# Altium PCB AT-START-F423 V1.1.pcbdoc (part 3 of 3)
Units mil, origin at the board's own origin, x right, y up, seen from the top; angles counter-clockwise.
Board outline 13392.89 x 3532.45 mil, 2 copper layers (Top Layer, Bottom Layer); 137 components, 162 nets, 618 pads, 618 vias.
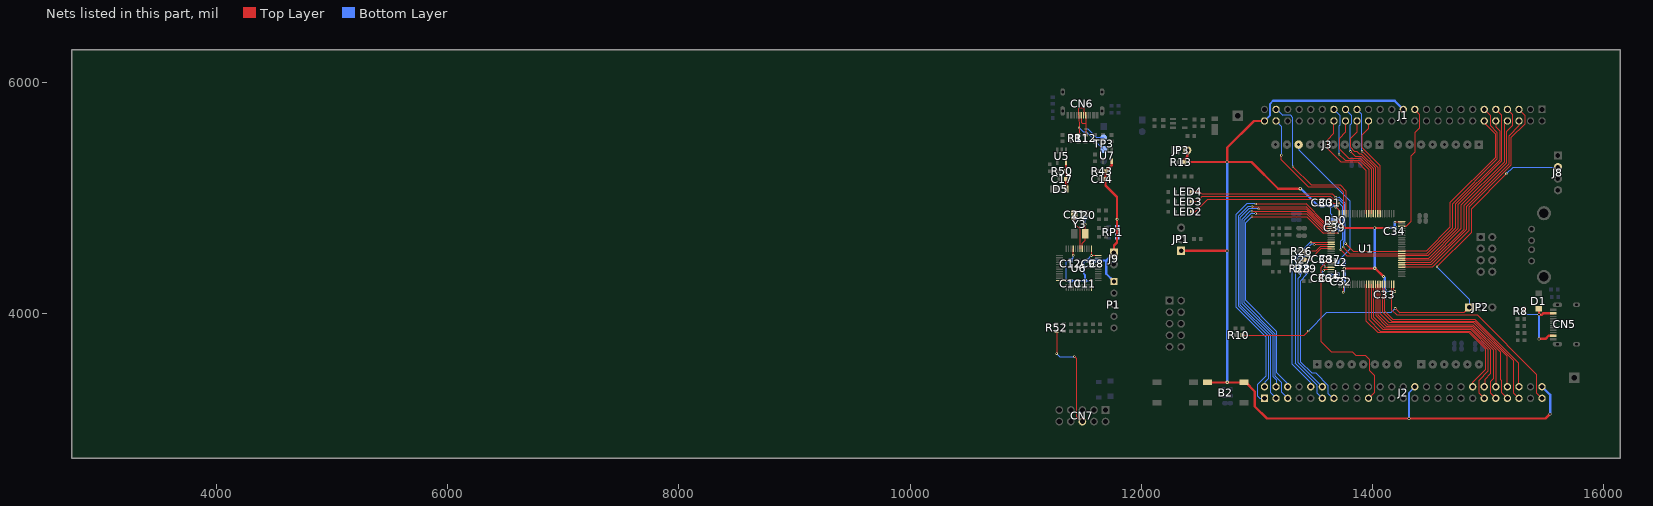
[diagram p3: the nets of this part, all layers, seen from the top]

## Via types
v1: diameter 19.68, hole 7.87, Top Layer to Bottom Layer, 317 vias
v2: diameter 19.7, hole 7.9, Top Layer to Bottom Layer, 187 vias
v3: diameter 19.7, hole 7.87, Top Layer to Bottom Layer, 72 vias
v4: diameter 27.56, hole 15.75, Top Layer to Bottom Layer, 31 vias
v5: diameter 23.62, hole 11.81, Top Layer to Bottom Layer, 11 vias

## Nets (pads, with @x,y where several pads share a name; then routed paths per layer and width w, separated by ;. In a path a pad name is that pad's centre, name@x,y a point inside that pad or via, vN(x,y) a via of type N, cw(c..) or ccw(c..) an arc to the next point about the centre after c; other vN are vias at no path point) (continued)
PD1: J1.32 U1.82 | length 889.2
  Top Layer w6: J1.32@13965.15,5665.15 13965.15,5600.69 13909.58,5545.11 13909.58,5432.11 14064.67,5277.01 U1.82@14064.67,4863.21
PD2: J1.33 U1.83 | length 976.4
  Top Layer w6: v3(13908.58,5402.11) 14044.98,5265.71 U1.83@14044.98,4863.21
  Bottom Layer w6: J1.33@13865.15,5765.15 13907.58,5722.73 13907.58,5403.11 v3(13908.58,5402.11)
PD3: J1.34 U1.84 | length 936.4
  Top Layer w6: J1.34@13865.15,5665.15 13865.15,5571.17 13810.58,5516.59 13810.58,5435.92 13846.38,5400.11 13868.58,5400.11 13890.58,5378.11 13907.58,5378.11 14025.27,5260.41 U1.84@14025.27,4863.21
PD4: J1.35 U1.85 | length 1036.1
  Top Layer w6: v3(13808.58,5402.11) 13850.58,5360.11 13899.58,5360.11 14005.67,5254.01 U1.85@14005.67,4863.21
  Bottom Layer w6: J1.35@13765.15,5765.15 13815.58,5714.73 13815.58,5639.11 13808.58,5632.11 v3(13808.58,5402.11)
PD5: J1.36 U1.86 | length 999.8
  Top Layer w6: J1.36@13765.15,5665.15 13765.15,5568.23 13709.58,5512.66 13709.58,5425.11 13791.58,5343.11 13894.58,5343.11 13985.98,5251.71 U1.86@13985.98,4863.21
PD6: J1.37 U1.87 | length 1106.9
  Top Layer w6: v3(13708.58,5377.11) 13761.58,5324.11 13888.58,5324.11 13966.27,5246.41 U1.87@13966.27,4863.21
  Bottom Layer w6: J1.37@13665.15,5765.15 13715.58,5714.73 13715.58,5628.11 13709.58,5622.11 13709.58,5378.11 v3(13708.58,5377.11)
PD7: J1.38 U1.88 | length 1049.8
  Top Layer w6: J1.38@13665.15,5665.15 13665.15,5557.69 13610.58,5503.11 13610.58,5424.11 13727.58,5307.11 13874.58,5307.11 13946.58,5235.11 U1.88@13946.58,4863.21
PD8: J1.5 U1.55 | length 1980.1
  Top Layer w6: U1.55@14251.67,4400.61 14515.91,4400.61 14830.58,4715.28 14830.58,4917.28 15195.58,5282.28 15195.58,5518.11 15314.58,5637.11 15314.58,5715.73 J1.5@15265.15,5765.15
PD9: J1.6 U1.56 | length 1814.6
  Top Layer w6: U1.56@14251.67,4420.31 14507.61,4420.31 14809.58,4722.28 14809.58,4924.28 15176.58,5291.28 15176.58,5534.11 15265.15,5622.69 J1.6@15265.15,5665.15
PD10: J1.7 U1.57 | length 1884.3
  Top Layer w6: U1.57@14251.67,4440.01 14500.31,4440.01 14786.58,4726.28 14786.58,4931.28 15156.58,5301.28 15156.58,5573.09 15207.58,5624.09 15207.58,5722.73 J1.7@15165.15,5765.15
PD11: J1.8 U1.58 | length 1724.6
  Top Layer w6: U1.58@14251.67,4459.71 14492.01,4459.71 14763.58,4731.28 14763.58,4936.28 15136.58,5309.28 15136.58,5636.58 J1.8@15165.15,5665.15
PD12: J1.9 U1.59 | length 1802.6
  Top Layer w6: U1.59@14251.67,4479.41 14484.71,4479.41 14741.58,4736.28 14741.58,4944.28 15117.58,5320.28 15117.58,5712.73 J1.9@15065.15,5765.15
PD13/LED2: J1.10 LED2.2 U1.60 | length 3958.6
  Top Layer w6: LED2.2@12436.83,4879.28 12466.58,4879.28 12574.89,4987.6 13625.89,4987.6 13659.38,4954.11 v3(13709.58,4954.11) ; v3(13725.58,4551.11) 13777.67,4499.01 U1.60@14251.67,4499.01 14476.31,4499.01 14716.58,4739.28 14716.58,4946.28 15097.58,5327.28 15097.58,5581.11 15065.15,5613.54 J1.10@15065.15,5665.15
  Bottom Layer w6: v3(13709.58,4954.11) 13735.58,4928.11 13735.58,4638.11 13725.58,4628.11 v3(13725.58,4551.11)
PD14/LED3: J1.11 LED3.2 U1.61 | length 4025.4
  Top Layer w6: LED3.2@12435.83,4965.28 12476.58,4965.28 12520.89,5009.6 13639.89,5009.6 13667.38,4982.11 v3(13700.58,4982.11) ; v3(13746.58,4575.11) 13802.98,4518.71 U1.61@14251.67,4518.71 14470.01,4518.71 14691.58,4740.28 14691.58,4949.28 15079.58,5337.28 15079.58,5564.11 15021.58,5622.11 15021.58,5708.73 J1.11@14965.15,5765.15
  Bottom Layer w6: v3(13700.58,4982.11) 13713.58,4982.11 13749.58,4946.11 13749.58,4626.47 13744.58,4621.47 13744.58,4577.11 v3(13746.58,4575.11)
PD15/LED4: J1.12 LED4.2 U1.62 | length 3854.8
  Top Layer w6: LED4.2@12434.83,5051.28 12503.96,5051.28 12524.98,5030.26 13656.42,5030.26 v3(13681.58,5005.11) ; v3(13766.58,4604.11) 13832.27,4538.41 U1.62@14251.67,4538.41 14461.71,4538.41 14668.5,4745.21 14668.5,4956.21 15059.58,5347.28 15059.58,5553.11 14965.15,5647.54 J1.12@14965.15,5665.15
  Bottom Layer w6: v3(13681.58,5005.11) 13710.37,5005.11 13763.58,4951.91 13763.58,4607.11 v3(13766.58,4604.11)
PE0: J1.47 U1.97 | length 1342.8
  Top Layer w6: v3(13310.58,5271.11) 13467.58,5114.11 13718.58,5114.11 13769.38,5063.31 U1.97@13769.38,4863.21
  Bottom Layer w6: J1.47@13165.15,5765.15 13170.54,5765.15 13221.58,5714.11 13290.58,5714.11 13310.58,5694.11 v3(13310.58,5271.11)
PE1: J1.48 U1.98 | length 1195.8
  Top Layer w6: v3(13210.58,5368.11) 13210.58,5328.11 13447.58,5091.11 13706.58,5091.11 13749.77,5047.91 U1.98@13749.77,4863.21
  Bottom Layer w6: J1.48@13165.15,5665.15 13210.58,5619.73 v3(13210.58,5368.11)
PE2: J2.1 U1.1 | length 2698.9
  Top Layer w6: v3(12988.58,4947.11) 13425.58,4947.11 13578.38,4794.31 U1.1@13641.48,4794.31
  Bottom Layer w6: v3(12988.58,4947.11) 12912.58,4947.11 12904.58,4939.11 12904.42,4939.11 12818.58,4853.27 12818.58,4056.91 13077.58,3797.91 13077.58,3457.11 13002.58,3382.11 13002.58,3290.11 13026.12,3266.57 J2.1@13065.15,3266.57
PE3: J2.2 U1.2 | length 2495.9
  Top Layer w6: v3(12958.58,4925.11) 13427.78,4925.11 13578.28,4774.61 U1.2@13641.48,4774.61
  Bottom Layer w6: v3(12958.58,4925.11) 12921.58,4925.11 12916.58,4920.11 12916.25,4920.11 12836.58,4840.43 12836.58,4065.91 13095.36,3807.13 13095.36,3437.89 13065.15,3407.69 J2.2@13065.15,3366.57
PE4: J2.3 U1.3 | length 2573.4
  Top Layer w6: v3(13012.58,4905.11) 13427.98,4905.11 13578.08,4755.01 U1.3@13641.48,4755.01
  Bottom Layer w6: v3(13012.58,4905.11) 12930.58,4905.11 12852.58,4827.11 12852.58,4077.91 13114.58,3815.91 13114.58,3317.14 J2.3@13165.15,3266.57
PE5: J2.4 U1.4 | length 2433.6
  Top Layer w6: v3(12956.58,4884.11) 13429.18,4884.11 13577.98,4735.31 U1.4@13641.48,4735.31
  Bottom Layer w6: v3(12956.58,4884.11) 12955.58,4883.11 12939.58,4883.11 12867.58,4811.11 12867.58,4087.91 13134.29,3821.2 13134.29,3456.11 13165.15,3425.25 J2.4@13165.15,3366.57
PE6: J2.5 U1.5 | length 2538.7
  Top Layer w6: v3(12988.58,4864.11) 13429.38,4864.11 13577.88,4715.61 U1.5@13641.48,4715.61
  Bottom Layer w6: v3(12988.58,4864.11) 12945.58,4864.11 12883.58,4802.11 12883.58,4096.91 13154.11,3826.38 13154.11,3460.58 13208.6,3406.08 13208.6,3323.11 J2.5@13265.15,3266.57
PE7: J2.38 U1.38 | length 1822.5
  Top Layer w6: U1.38@13946.58,4253.01 13946.58,3934.11 14046.58,3834.11 14835.98,3834.11 14977.58,3692.51 14977.58,3520.11 14865.15,3407.69 J2.38@14865.15,3366.57
PE8: J2.39 U1.39 | length 1920
  Top Layer w6: U1.39@13966.27,4253.01 13966.27,3949.41 14067.58,3848.11 14841.78,3848.11 14997.58,3692.31 14997.58,3500.11 14917.58,3420.11 14917.58,3314.14 J2.39@14965.15,3266.57
PE9: J2.40 U1.40 | length 1782.1
  Top Layer w6: U1.40@13985.98,4253.01 13985.98,3962.71 14086.58,3862.11 14847.58,3862.11 15018.58,3691.11 15018.58,3479.11 14968.46,3429 14968.46,3369.88 J2.40@14965.15,3366.57
PE10: J2.41 U1.41 | length 1886.2
  Top Layer w6: U1.41@14005.67,4253.01 14005.67,3973.01 14102.58,3876.11 14853.98,3876.11 15041.58,3688.51 15041.58,3434.11 15016.58,3409.11 15016.58,3315.14 J2.41@15065.15,3266.57
PE11: J2.42 U1.42 | length 1751.4
  Top Layer w6: U1.42@14025.27,4253.01 14025.27,3983.41 14118.58,3890.11 14859.78,3890.11 15063.58,3686.31 15063.58,3430.11 15065.15,3428.54 J2.42@15065.15,3366.57
PE12: J2.43 U1.43 | length 1881
  Top Layer w6: U1.43@14044.98,4253.01 14044.98,3989.71 14130.58,3904.11 14865.58,3904.11 15101.58,3668.11 15101.58,3433.11 15113.58,3421.11 15113.58,3318.14 J2.43@15165.15,3266.57
PE13: J2.44 U1.44 | length 1771.1
  Top Layer w6: U1.44@14064.67,4253.01 14064.67,3997.01 14143.58,3918.11 14875.58,3918.11 15165.15,3628.54 J2.44@15165.15,3366.57
PE14: J2.45 U1.45 | length 1894.4
  Top Layer w6: U1.45@14084.38,4253.01 14084.38,4014.11 14166.37,3932.11 14881.38,3932.11 15217.58,3595.92 15217.58,3314.14 J2.45@15265.15,3266.57
PE15: J2.46 U1.46 | length 1783.6
  Top Layer w6: U1.46@14104.08,4253.01 14104.08,4018.61 14176.58,3946.11 14887.18,3946.11 15265.15,3568.14 J2.46@15265.15,3366.57
PF0/HEXT_IN: R26.1 R28.1 U1.12 | length 389
  Top Layer w6: v3(13416.58,4505.11) 13418.54,4507.07 13418.54,4538.08 13507.54,4538.08 13547.27,4577.81 U1.12@13641.48,4577.81
  Bottom Layer w6: R28.1@13373.58,4407.11 13373.58,4462.11 v3(13416.58,4505.11)
PF0_E: J2.12 R28.2 | length 1093.7
  Bottom Layer w6: R28.2@13373.58,4362.71 13373.58,4324.11 13351.58,4302.11 13351.58,3580.14 J2.12@13565.15,3366.57
PF1/HEXT_OUT: R27.1 R29.1 U1.13 | length 332.4
  Top Layer w6: R27.1@13418.54,4465.07 13418.54,4464.08 13459.54,4464.08 13553.58,4558.11 U1.13@13641.48,4558.11
  Bottom Layer w6: R29.1@13426.58,4409.23 13426.58,4432.11 v3(13459.58,4465.11)
PF1_E: J2.13 R29.2 | length 1266.6
  Bottom Layer w6: R29.2@13425.3,4364.83 R29.2@13426.58,4364.83 13426.58,4333.11 13374.58,4281.11 13374.58,3584.11 13471.58,3487.11 13506.58,3487.11 13612.58,3381.11 13612.58,3311.11 13657.12,3266.57 J2.13@13665.15,3266.57
PF2: J2.19 U1.19 | length 1602.3
  Top Layer w6: U1.19@13641.48,4440.01 13595.48,4440.01 13554.58,4399.11 13554.58,3756.11 13643.08,3667.6 13824.08,3667.6 13853.59,3638.1 13935.59,3638.1 13969.58,3604.11 13969.58,3510.41 14015.58,3464.41 14015.58,3316.99 J2.19@13965.15,3266.57
PF6: J1.23 U1.73 | length 1116.4
  Top Layer w6: U1.73@14251.67,4755.01 14289.99,4755.01 14334.58,4799.6 14334.58,5364.11 14369.58,5399.11 14369.58,5566.11 14409.58,5606.11 14409.58,5720.73 J1.23@14365.15,5765.15
PF8: J2.49 U1.49 | length 1933.6
  Top Layer w6: U1.49@14163.08,4253.01 14163.08,4033.41 14208.38,3988.11 14904.58,3988.11 15416.58,3476.11 15416.58,3315.14 J2.49@15465.15,3266.57
PF9: J2.10 U1.10 | length 1564.6
  Top Layer w6: v3(13466.58,4617.11) 13466.67,4617.21 U1.10@13641.48,4617.21
  Bottom Layer w6: J2.10@13465.15,3366.57 13465.15,3400.54 13303.58,3562.11 13303.58,4462.11 13458.58,4617.11 v3(13466.58,4617.11)
PF10: J2.11 U1.11 | length 1659.3
  Top Layer w6: v3(13495.58,4597.11) 13495.98,4597.51 U1.11@13641.48,4597.51
  Bottom Layer w6: v3(13495.58,4597.11) 13467.58,4597.11 13330.58,4460.11 13330.58,3570.11 13329.58,3569.11 13515.58,3383.11 13515.58,3316.14 J2.11@13565.15,3266.57
SWO: CN7.6 R52.2 | length 953.3
  Top Layer w6: v1(11267.88,3653.08) 11268.28,3653.48 R52.2@11268.28,3847.02 ; v1(11420.88,3628.08) 11422.32,3628.08 11437.6,3612.8 11437.6,3113.36 11485.28,3065.68 CN7.6@11490.38,3065.68
  Bottom Layer w6: v1(11267.88,3653.08) 11293.88,3627.08 11419.88,3627.08 v1(11420.88,3628.08)
USART1_TX: J8.2 JP2.1 R10.2 | length 4080.8
  Top Layer w6: R10.2@12874.21,3812.6 13407.89,3812.6 v3(13443.89,3848.6) ; v2(14195.89,4044.6) 14232.89,4007.6 14789.89,4007.6 JP2.1@14834.9,4052.6 ; v2(14555.89,4403.6) 14850.89,4698.6 14850.89,4902.6 v2(15155.89,5207.6)
  Bottom Layer w6: v3(13443.89,3848.6) 13605.41,4010.11 14161.41,4010.11 v2(14195.89,4044.6) ; v2(14555.89,4403.6) 14834.89,4124.6 JP2.1@14834.9,4052.6 ; v2(15155.89,5207.6) 15214.41,5266.11 J8.2@15602.58,5266.11
USB+: CN6.A6 CN6.B6 R11.1 TP3.3 | length 626.2
  Top Layer w6: R11.1@11458.28,5545.34 11461.28,5548.34 v1@11461.28,5603.3 ; v1(11461.28,5605.68) v1@11461.28,5603.3 ; CN6.A6@11500.2,5715.38 11500.2,5773.75 11493.28,5780.68 11468.28,5780.68 11460.9,5773.3 CN6.B6@11460.9,5715.38 v1@11461.28,5603.3
  Bottom Layer w6: v1(11461.28,5605.68) 11501.28,5565.68 11527.08,5565.68 TP3.3@11674.63,5418.13
USB-: CN6.A7 CN6.B7 R12.1 TP3.2 | length 463.3
  Top Layer w6: CN6.A7@11480.6,5715.38 11480.6,5653.35 11488.28,5645.68 11519.56,5645.68 ; R12.1@11518.28,5545.34 11519.56,5546.62 11519.56,5645.68 ; CN6.B7@11519.9,5715.38 11519.9,5646.02 11519.56,5645.68
  Bottom Layer w6: v1(11518.28,5595.68) 11538.28,5595.68 11615.83,5518.13 TP3.2@11674.63,5518.13
VBAT: C39.2 J2.6 R30.1 U1.6 | length 2559
  Top Layer w10: v3(12956.58,4838.11) 13430.58,4838.11 13572.77,4695.91 U1.6@13641.48,4695.91 13641.67,4696.11 v3(13700.58,4696.11)
  Bottom Layer w10: v3(12956.58,4838.11) 12901.52,4783.06 12901.52,4112.96 13171.58,3842.91 13171.58,3487.11 13265.15,3393.54 J2.6@13265.15,3366.57 ; v3(13700.58,4696.11) 13702.14,4697.67 C39.2@13702.14,4741.11 13701.24,4742.01 R30.1@13701.24,4806.11
  other v3: 12956.58,4838.11
VBUS: CN5.A4B9 CN5.B4A9 D1.1 R8.2 | length 741
  Top Layer w6: R8.2@15311.89,4017.6 v2(15311.89,4056.6)
  Top Layer w20: D1.1@15436.89,4039.7 15437.89,4038.7 v4(15437.89,3990.6) 15463.96,3990.6 15474.98,4001.61 CN5.B4A9@15562.27,4001.61 ; v4(15437.89,3780.6) 15493.71,3780.6 15521.73,3808.61 CN5.A4B9@15562.27,3808.61
  Bottom Layer w6: v2(15311.89,4056.6) 15311.89,4017.6 15338.89,3990.6 v4(15437.89,3990.6)
  Bottom Layer w20: v4@15436.89,3991.6 v4(15437.89,3990.6) v4(15437.89,3780.6)
VCC: C8.2 C9.2 C10.2 C11.2 C12.2 C14.2 J9.1 P1.1 R43.2 RP1.1 RP1.2 RP1.3 RP1.4 U6.1 U6.9 U6.24 U6.36 U6.48 U7.5 | length 2525.7
  Top Layer w10: U6.24@11292.68,4285.08 11350.69,4285.09 v5(11351.28,4285.68) ; v5(11410.28,4502.68) 11410.79,4503.19 U6.9@11410.79,4560.67 ; U6.36@11568.27,4226.03 11568.27,4282.67 v5(11569.28,4283.68) ; U6.1@11568.27,4560.67 v5(11568.28,4501.68) U6.48@11627.28,4501.68
  Top Layer w20: U7.5@11743.27,5315.68 11743.27,5281.01 R43.2@11692.94,5230.68 11692.94,5162.78 C14.2@11690.84,5160.68 11690.84,5108.12 11790.28,5008.68 v5(11790.28,4814.41) 11790.28,4614.84 11763.28,4587.84 J9.1@11763.28,4525.68
  Bottom Layer w10: C10.2@11388.28,4284.24 11352.72,4284.24 v5(11351.28,4285.68) 11351.28,4448.68 11360.84,4458.24 C12.2@11388.28,4458.24 11410.28,4480.24 v5(11410.28,4502.68) ; C11.2@11513.28,4283.24 11568.84,4283.24 v5(11569.28,4283.68) ; C9.2@11543.28,4458.24 11543.28,4476.68 v5(11568.28,4501.68) ; v5(11790.28,4814.41) 11790.28,4651.38 RP1.4@11791.28,4650.38
  Bottom Layer w15: C10.2@11388.28,4284.24 C11.2@11513.28,4283.24 11513.28,4333.68 11502.28,4344.68 11502.28,4449.68 11510.84,4458.24 C9.2@11543.28,4458.24
  Bottom Layer w20: C9.2@11543.28,4458.24 C8.2@11613.28,4458.24 11695.84,4458.24 ; P1.1@11763.28,4275.68 11695.84,4343.12 11695.84,4458.24 ; J9.1@11763.28,4525.68 11695.84,4458.24
VCC3.5V: C17.2 D5.2 R50.2 U5.5 | length 237.7
  Top Layer w20: U5.5@11348.28,5310.68 11348.28,5231.02 R50.2@11347.94,5230.68 11347.94,5162.78 C17.2@11345.84,5160.68 11350.03,5156.49 D5.2@11350.03,5075.68
VDD: B2.1 B2.2 C30.2 C31.2 C32.2 C33.2 C34.2 J1.25 J1.50 J2.28 J2.50 JP1.1 JP3.2 L1.1 L2.1 R13.2 R30.2 U1.28 U1.50 U1.75 U1.100 | length 11815.7
  Top Layer w10: v4(13680.58,4923.11) 13710.58,4893.11 13710.58,4863.41 U1.100@13710.38,4863.21 13710.38,4803.31 13710.58,4803.11 ; v5(13745.58,4183.11) 13749.77,4187.31 U1.28@13749.77,4253.01 ; U1.50@14182.77,4253.01 14182.77,4198.91 v5(14191.58,4190.11) ; v3(14192.58,4788.11) 14198.77,4794.31 U1.75@14251.67,4794.31
  Top Layer w20: JP1.1@12343.89,4542.08 12741.41,4542.08 v4(12741.89,4541.6) ; JP3.2@12396.58,5411.11 12396.58,5358.11 12375.24,5336.77 12375.24,5310.11 12795.73,5310.11 ; B2.1@12573.09,3403.69 v4@12741.16,3403.69 ; v4(12742.58,3405.11) v4@12741.16,3403.69 ; J1.50@13065.15,5665.15 12973.61,5665.15 12741.89,5433.43 v4(12741.89,5310.6) 12953.69,5310.6 13184.69,5079.6 v4(13374.89,5079.6) ; 13710.58,4803.11 13710.58,4788.11 13758.58,4740.11 v4(14017.58,4740.11) v5(14137.58,4740.11) ; v4(13754.17,4389.66) 14016.12,4389.66 v4(14018.58,4392.11) 14021.58,4392.11 v5(14093.58,4320.11) ; v4(15534.58,3131.11) 15495.58,3092.11 v4(14315.58,3092.11) 13085.58,3092.11 12981.58,3196.11 12981.58,3326.11 12904,3403.69 B2.2@12888.06,3403.69 v4@12741.16,3403.69
  Bottom Layer w10: C31.2@13634.58,4930.55 13634.58,4865.11 13645.58,4854.11 13645.58,4809.77 R30.2@13641.92,4806.11 ; v5(13745.58,4183.11) 13756.14,4193.67 C32.2@13756.14,4275.11 ; C33.2@14105.58,4191.67 14190.01,4191.67 v5(14191.58,4190.11)
  Bottom Layer w15: J1.50@13065.15,5665.15 13113.58,5713.58 13113.58,5814.11 13136.58,5837.11 ; v4(14315.58,3092.11) 14314.58,3093.11 14314.58,3315.99 J2.28@14365.15,3366.57
  Bottom Layer w20: v4(12741.89,5310.6) v4(12741.89,4541.6) 12741.89,3405.79 v4(12742.58,3405.11) ; 13136.58,5837.11 13139.58,5840.11 14190.19,5840.11 J1.25@14265.15,5765.15 ; v4(13374.89,5079.6) 13380.09,5079.6 13529.14,4930.55 C30.2@13564.58,4930.55 C31.2@13634.58,4930.55 13673.14,4930.55 v4(13680.58,4923.11) ; L2.1@13753.17,4444.11 13754.17,4443.11 v4(13754.17,4389.66) L1.1@13754.17,4339.11 13756.14,4337.15 C32.2@13756.14,4275.11 ; v4(14017.58,4740.11) 14018.58,4739.11 v4(14018.58,4392.11) ; v5(14093.58,4320.11) 14105.58,4308.11 C33.2@14105.58,4191.67 ; v5(14137.58,4740.11) 14138.14,4740.67 C34.2@14192.58,4740.67 v3(14192.58,4788.11) ; J2.50@15465.15,3366.57 15534.58,3297.14 v4(15534.58,3131.11)
VDDA: C35.2 C36.2 L1.2 U1.22 | length 253.7
  Top Layer w10: v1(13576.58,4371.11) 13586.38,4380.91 U1.22@13641.48,4380.91
  Bottom Layer w10: v1(13576.58,4371.11) 13561.58,4356.11 C36.2@13561.58,4332.67 13629.58,4332.67 C35.2@13630.58,4333.67 13693.53,4333.67 L1.2@13698.98,4339.11
VREF+: C37.2 C38.2 J3.8 L2.2 U1.21 | length 1477.4
  Top Layer w10: v1(13588.58,4404.11) 13591.58,4401.11 13640.98,4401.11 U1.21@13641.48,4400.61
  Bottom Layer w10: J3.8@13359.5,5460.43 13359.5,5415.19 13801.58,4973.11 13801.58,4554.11 13691.01,4443.55 C37.2@13631.58,4443.55 C38.2@13563.58,4443.55 13563.58,4429.11 v1(13588.58,4404.11)
Y3_1: C20.2 U6.5 Y3.1 | length 274.7
  Top Layer w6: U6.5@11489.53,4560.67 11489.53,4606.93 11515.52,4632.92 Y3.1@11515.52,4689.97 11515.52,4771.44 v1(11515.28,4771.68)
  Bottom Layer w6: v1(11515.28,4771.68) 11515.28,4823.12 C20.2@11516.28,4824.12
Y3_3: C21.2 U6.6 Y3.3 | length 362.4
  Top Layer w6: Y3.3@11421.04,4851.39 11425.28,4847.15 v1(11425.28,4773.68) 11469.85,4729.1 U6.6@11469.85,4560.68
  Bottom Layer w6: v1(11425.28,4773.68) C21.2@11425.28,4825.12
pads on no net: CN5.A8 CN5.B8 CN6.A8 CN6.B8 J2.21 J2.22 J4.1 J4.8 U6.2 U6.3 U6.4 U6.14 U6.15 U6.16 U6.17 U6.18 U6.21 U6.22 U6.29 U6.38 U6.41 U6.42 U6.43 U6.45 U6.46

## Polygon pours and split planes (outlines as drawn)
GND on Top Layer (solid, remove dead copper, pour order 0): 11124.19,3001.55 15892.89,3001.55 15892.89,6032.45 11124.19,6032.45
GND on Bottom Layer (solid, remove dead copper, pour order 4): 11124.89,3000.6 15892.89,3000.6 15892.89,6031.6 11124.89,6031.6

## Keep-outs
Top Layer:
  region: 11617.28,4449.68 11650.28,4449.68 11650.28,4442.68 11617.28,4442.68
Board Outline Layer:
  lines w8: 11856.57,3606.13 11856.57,3698.13 11895.84,3698.13 11895.84,3606.13 11856.57,3606.13 ; 11856.58,4903.13 11856.58,5553.13 11895.84,5553.13 11895.84,4903.39 11856.58,4903.13
  lines w10: 11124.86,5950 ccw(c11128.2,5947.79) 11124.19,5947.78 ; 11206.29,3000.34 ccw(c11207.62,3004.13) 11207.62,3000.11 ; 11774.65,3000.78 ccw(c11777.58,3079.47) 11856.32,3079.47 11856.57,3518.13 11895.84,3518.13 11895.84,3079.47 ccw(c11974.58,3079.47) 11974.58,3000.73 ; 11777.58,6030.02 cw(c11777.58,5951.28) 11856.32,5951.28 11856.32,5631.13 11895.83,5631.13 11895.83,5951.02 cw(c11974.57,5951.03) 11974.57,6029.77 ; 11894.84,4825.13 11856.58,4825.13 11856.57,3809.13 11895.58,3809.13 11895.58,4824.39 ; 11973.95,3000.16 ccw(c11974.57,3004.13) 11974.57,3000.11 ; 11974.57,6030.54 ccw(c11974.6,6034.56) 11974.6,6030.54 ; 15891.94,3080.95 15891.94,3079.06 cw(c15812.88,3079.06) 15812.88,3000 15812.77,3000.11 15810.99,3000.11 15255.83,3000.11 11974.58,3000.11 cw(c11973.94,3008.08) 11973.32,3000.11 11207.62,3000.11 ; 15891.94,3081.06 15891.94,5947.83 15891.94,5951.48 ccw(c15812.88,5951.48) 15812.88,6030.54 15255.83,6030.54 11974.52,6030.54 11207.58,6030.54 11206.94,6030.54 ccw(c11206.94,5947.78) 11124.19,5947.78 ; 11124.19,5947.78 11124.6,3083.08 ccw(c11207.58,3083.08) 11207.58,3000.11 ; 11207.58,3000.11 11207.62,3000.11
Multi-Layer:
  circle w10: c15760.05,5897.28 r62.99
  circle w10: c15760.05,3122.6 r62.99
  circle w10: c12019.89,3122.6 r62.99
  circle w10: c12019.89,5897.28 r62.99
  circle w10: c15019.5,4860.43 r62.99
  circle w10: c12969.5,3560.43 r62.99
  circle w10: c13019.5,5460.43 r62.99
  circle w10: c11373.1,5772.28 r13.8
  circle w10: c11607.7,5772.28 r13.8
  circle w10: c15619.17,4022.41 r13.8
  circle w10: c15619.17,3787.81 r13.8

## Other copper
Top Layer:
  drawing of 635 lines, arcs and shapes, not listed
Bottom Layer:
  drawing of 356 lines, arcs and shapes, not listed

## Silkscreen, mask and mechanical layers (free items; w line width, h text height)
Top Silkscreen Layer:
  lines w5: 14798.13,5322.68 14800.13,5322.68 ; 14939.13,5337.68 14937.13,5337.68 ; 14800.13,5322.68 14819.13,5341.68 14819.13,5346.68 ; 14800.13,5322.68 14836.13,5322.68 ; 14800.13,5322.68 14802.13,5322.68 14819.13,5339.68 ; 14819.13,5322.68 14816.13,5325.68 14805.13,5325.68 14806.13,5324.68 14811.13,5324.68 14817.63,5331.18 14819.13,5331.18 14827.63,5322.68 14836.13,5322.68 ; 14819.13,5322.68 14819.13,5339.68 ; 14819.13,5322.68 14824.13,5327.68 ; 14819.13,5339.68 14824.13,5334.68 14824.13,5327.68 ; 14819.13,5339.68 14839.13,5319.68 ; 14819.13,5339.68 14819.13,5346.68 ; 14819.13,5346.68 14817.13,5346.68 14790.13,5319.68 14839.13,5319.68 ; 14819.13,5346.68 14846.13,5319.68 14839.13,5319.68 ; 14824.13,5327.68 14831.13,5327.68 14836.13,5322.68 ; 14836.13,5322.68 14839.13,5319.68 ; 14898.13,5340.68 14947.13,5340.68 14920.13,5313.68 14918.13,5313.68 ; 14898.13,5340.68 14891.13,5340.68 14918.13,5313.68 ; 14898.13,5340.68 14901.13,5337.68 ; 14898.13,5340.68 14918.13,5320.68 ; 14901.13,5337.68 14909.63,5337.68 14918.13,5329.18 14919.63,5329.18 14926.13,5335.68 14931.13,5335.68 14932.13,5334.68 14921.13,5334.68 14918.13,5337.68 ; 14901.13,5337.68 14906.13,5332.68 14913.13,5332.68 ; 14901.13,5337.68 14937.13,5337.68 ; 14913.13,5332.68 14918.13,5337.68 ; 14913.13,5332.68 14913.13,5325.68 14918.13,5320.68 ; 14918.13,5313.68 14918.13,5320.68 ; 14918.13,5313.68 14918.13,5318.68 14937.13,5337.68 ; 14918.13,5320.68 14918.13,5337.68 ; 14918.13,5320.68 14935.13,5337.68 14937.13,5337.68
  lines w6: 11339.27,3292.39 11339.27,3591.39 ; 11439.27,3293.39 11439.27,3592.39 ; 11539.27,3293.39 11539.27,3593.39 ; 11641.27,3292.39 11641.27,3586.39 ; 14398.89,4003.6 14398.89,4091.6 ; 14578.89,4003.6 14578.89,4091.6 ; 14758.89,4010.6 14758.89,4091.6 ; 14758.89,4091.6 14758.89,4003.6 14219.89,4003.6 14219.89,4091.6 14758.89,4091.6
  lines w8: 11437.62,3218.13 11437.62,3258.13 11537.62,3258.13 11537.62,3217.13 ; 11728.17,3272.13 11691.17,3235.13 11652.17,3274.13 11728.17,3274.13 ; 12123.27,4147.31 12123.27,4071.31 12162.27,4110.31 12125.27,4147.31 ; 12186.27,3860.31 12146.27,3860.31 12146.27,3960.31 12187.27,3960.31
  lines w10: 13545.72,5192.83 14961.42,5192.83 ; 13802.63,3853.68 14255.63,3853.68 ; 14414.13,3853.68 14974.13,3853.68
  text "99" at 13029.99,5948.21 h38.28
  text "91" at 13434.99,5948.21 h38.28
  text "81" at 13937.84,5948.21 h38.28
  text "71" at 14435.99,5948.21 h38.28
  text "61" at 14930.99,5948.21 h38.28
  text "51" at 15429.99,5948.21 h38.28
  text "E0" at 13154.23,5835.43 h34.45 r45
  text "B3" at 13558.23,5835.43 h34.45 r45
  text "B8" at 13259.23,5834.43 h34.45 r45
  text "B5" at 13457.23,5834.43 h34.45 r45
  text "D4" at 13750.23,5834.43 h34.45 r45
  text "F6" at 14355.43,5834.45 h34.45 r45
  text "B7" at 13360.23,5833.43 h34.45 r45
  text "D8" at 15249.32,5833.47 h34.45 r45
  text "D6" at 13651.23,5832.43 h34.45 r45
  text "D10" at 15153.16,5832.37 h34.45 r45
  text "D2" at 13854.23,5831.43 h34.45 r45
  text "A8" at 14656.23,5831.43 h34.45 r45
  text "D12" at 15060.16,5831.37 h34.45 r45
  text "D0" at 13951.23,5830.43 h34.45 r45
  text "A12" at 14446.28,5830.3 h34.45 r45
  text "A10" at 14544.25,5830.3 h34.45 r45
  text "D14" at 14951.16,5830.37 h34.45 r45
  text "B12" at 15444.25,5829.4 h34.45 r45
  text "A15" at 14160.16,5827.37 h34.45 r45
  text "C6" at 14849.23,5827.43 h34.45 r45
  text "B14" at 15338.25,5827.4 h34.45 r45
  text "GND" at 13035.16,5825.37 h34.45 r45
  text "C8" at 14743.23,5825.43 h34.45 r45
  text "C11" at 14049.16,5823.37 h34.45 r45
  text "VDD" at 14255.16,5823.37 h34.45 r45
  text "GND" at 12762.14,5561.87 h51.92
  text "B9" at 13254.23,5537.43 h34.45 r45
  text "E1" at 13157.23,5536.43 h34.45 r45
  text "B4" at 13548.23,5533.43 h34.45 r45
  text "D1" at 13964.23,5533.43 h34.45 r45
  text "A9" at 14649.54,5530.69 h34.45 r45
  text "C7" at 14858.23,5531.43 h34.45 r45
  text "D9" at 15256.32,5531.47 h34.45 r45
  text "C9" at 14750.23,5530.43 h34.45 r45
  text "B6" at 13451.23,5529.37 h34.45 r45
  text "D7" at 13648.23,5529.43 h34.45 r45
  text "D3" at 13858.23,5526.43 h34.45 r45
  text "D5" at 13752.23,5525.43 h34.45 r45
  text "C12" at 14046.16,5523.37 h34.45 r45
  text "C10" at 14145.16,5523.37 h34.45 r45
  text "A11" at 14543.03,5523.18 h34.45 r45
  text "D13" at 15043.16,5522.37 h34.45 r45
  text "D15" at 14949.16,5521.37 h34.45 r45
  text "D11" at 15150.16,5521.37 h34.45 r45
  text "A13" at 14440.25,5520.4 h34.45 r45
  text "VDD" at 13036.75,5519.25 h34.45 r40
  text "A14" at 14233.16,5518.37 h34.45 r45
  text "B15" at 15349.25,5518.4 h34.45 r45
  text "B13" at 15450.46,5516.33 h34.45 r45
  text "BOOT0" at 13304.2,5514.35 h28.71 r30
  text "GND" at 14334.16,5514.37 h34.45 r45
  text "IDD" at 12104.96,5386.36 h46.08
  text "1" at 14840.7,5366.84 h46.27 r90
  text "4" at 14536.35,5353.68 h45.56 r90
  text "2" at 14740.35,5353.68 h45.56 r90
  text "8" at 14085.42,5351.08 h45.56 r90
  text "7" at 14245.35,5350.68 h45.56 r90
  text "3V3" at 15419.14,5345.86 h40.19
  text "13" at 13585.54,5324.7 h45.94 r90
  text "12" at 13683.54,5324.7 h45.94 r90
  text "#6" at 14338.54,5308 h45.94 r90
  text "#5" at 14440.54,5308 h45.94 r90
  text "#9" at 13984.54,5307 h45.94 r90
  text "#3" at 14639.54,5307 h45.94 r90
  text "#11" at 13785.54,5294.65 h45.94 r90
  text "#10" at 13884.54,5276.95 h45.94 r90
  text "SCL" at 13182.54,5261.75 h45.94 r90
  text "GND" at 13482.54,5257.35 h45.94 r90
  text "SDA" at 13284.54,5255.15 h45.94 r90
  text "USART1_TX" at 15182.55,5249.86 h40.19
  text "TX" at 14838.54,5222.93 h45.94 r90
  text "DIGITAL(#=PWM)" at 13941.74,5221.94 h40.19
  text "RX 0" at 14942.54,5216.9 h45.94 r90
  text "AREF" at 13381.54,5205.3 h45.94 r90
  text "USART1_RX" at 15181.55,5144.86 h40.19
  text "GND" at 15421.14,5047.86 h40.19
  text "AT-Link-EZ V1.3" at 11172.52,5015.49 h57.42 r270
  text "LD:" at 11775.35,5009.75 h40.19 r270
  text "1" at 11777.69,4892.38 h39.87 r270
  text "2" at 11776.69,4825.38 h39.87 r270
  text "3" at 11775.69,4752.38 h39.87 r270
  text "GND" at 12140.2,4729.94 h40.19
  text "4" at 11776.69,4677.38 h39.87 r270
  text "5V" at 15119.54,4644.94 h40.19
  text "MISO" at 14713.57,4643.94 h40.19
  text "BOOT0" at 12054.24,4619.94 h40.19
  text "MOSI" at 15108.57,4542.94 h40.19
  text "SCK" at 14734.05,4540.94 h40.19
  text "VDD" at 12139.2,4516.94 h40.19
  text "GND" at 15109.05,4444.94 h40.19
  text "RESET" at 14663.09,4440.94 h40.19
  text "NSS" at 14734.05,4339.94 h40.19
  text "PB11" at 15113.57,4335.94 h40.19
  text "AT-Link" at 12137.9,4213.88 h51.92
  text "USB_HOST" at 15472.88,4187.31 h45.94
  text "USART1" at 14193.17,4109.35 h40.19
  text "USB" at 14612.46,4109.35 h40.19
  text "5V" at 12423.69,4093.94 h40.19
  text "3V3" at 11987.2,4087.94 h40.19
  text "TX" at 14272.23,4028.34 h40.19
  text "PA9" at 14430.46,4028.34 h40.19
  text "VBUS" at 14587.7,4028.34 h40.19
  text "SWD" at 11991.2,3993.94 h40.19
  text "BOOT0" at 12422.24,3988.94 h40.19
  text "SWO" at 12425.39,3892.34 h40.19
  text "SWC" at 11988.2,3890.94 h40.19
  text "AT-START-F423 V1.1" at 12911.77,3885.02 h71.39
  text "NRST" at 11992.72,3790.94 h40.19
  text "USART1_RX" at 12420.3,3790.94 h40.19
  text "POWER" at 14037.09,3789.94 h40.19
  text "ANALOG IN" at 14562.15,3789.94 h40.19
  text "USART1_TX" at 12420.3,3689.94 h40.19
  text "GND" at 11993.2,3688.94 h40.19
  text "AN0" at 14432.84,3633.6 h45.94 r90
  text "AN1" at 14528.84,3633.6 h45.94 r90
  text "AN2" at 14633.84,3632.6 h45.94 r90
  text "AN3" at 14734.84,3632.6 h45.94 r90
  text "AN4" at 14836.84,3632.6 h45.94 r90
  text "AN5" at 14936.84,3632.6 h45.94 r90
  text "5V" at 13940.54,3632 h45.94 r90
  text "3.3V" at 13838.54,3630.9 h45.94 r90
  text "GND" at 14039.54,3631.45 h45.94 r90
  text "GND" at 14140.83,3631.45 h45.94 r90
  text "IOREF" at 13640.54,3630.34 h45.94 r90
  text "RESET" at 13737.54,3629.34 h45.94 r90
  text "USB_DEVICE" at 15414.85,3629.31 h45.94
  text "SWD" at 11569.56,3591.04 h40.19 r270
  text "GND" at 11264.63,3586.51 h40.19 r270
  text "NRST" at 11365.55,3587.23 h40.19 r270
  text "SWC" at 11470.55,3586.75 h40.19 r270
  text "3V3" at 11670.63,3586.51 h40.19 r270
  text "B1" at 14754.53,3438.01 h34.45 r45
  text "E3" at 13053.23,3434.43 h34.45 r45
  text "A1" at 14155.23,3434.43 h34.45 r45
  text "E11" at 15058.16,3433.5 h34.45 r45
  text "B11" at 15345.16,3433.97 h34.45 r45
  text "E5" at 13152.23,3433.43 h34.45 r45
  text "E7" at 14856.23,3432.76 h34.45 r45
  text "E9" at 14953.23,3433.29 h34.45 r45
  text "E13" at 15161.16,3432.73 h34.45 r45
  text "E15" at 15256.16,3432.73 h34.45 r45
  text "NC" at 14054.23,3432.43 h34.45 r45
  text "A5" at 14450.23,3432.43 h34.45 r45
  text "C5" at 14658.23,3432.43 h34.45 r45
  text "F9" at 13448.23,3431.43 h34.45 r45
  text "C1" at 13753.23,3431.43 h34.45 r45
  text "A3" at 14250.23,3430.43 h34.45 r45
  text "A7" at 14554.23,3429.43 h34.45 r45
  text "VDD" at 15455.16,3428.37 h34.45 r45
  text "C3" at 13858.23,3427.43 h34.45 r45
  text "F0*" at 13544.16,3423.37 h34.45 r45
  text "BOOT0" at 11573.98,3422.21 h30.14 r270
  text "C14*" at 13340.09,3422.42 h34.45 r45
  text "SWO" at 11471.54,3421.46 h40.19 r270
  text "NRST" at 13636.92,3420.02 h25.96 r45
  text "GND" at 13935.16,3418.37 h34.45 r45
  text "VDD" at 14331.16,3417.37 h34.45 r45
  text "VDD" at 13246.16,3415.53 h34.45 r45
  text "RX" at 11264.54,3397.98 h40.19 r270
  text "TX" at 11365.55,3396.68 h40.19 r270
  text "5V" at 11664.54,3396.68 h40.19 r270
  text "GND" at 15668.65,3287.83 h45.94
  text "F2" at 13952.23,3138.43 h34.45 r45
  text "C2" at 13858.23,3137.43 h34.45 r45
  text "B0" at 14750.23,3137.43 h34.45 r45
  text "A6" at 14556.23,3136.43 h34.45 r45
  text "E6" at 13254.23,3135.43 h34.45 r45
  text "C0" at 13759.23,3135.43 h34.45 r45
  text "A2" at 14255.23,3135.43 h34.45 r45
  text "F1*" at 13647.16,3134.37 h34.45 r45
  text "A0" at 14144.23,3134.43 h34.45 r45
  text "A4" at 14452.23,3134.43 h34.45 r45
  text "B2" at 14850.23,3134.43 h34.45 r45
  text "E4" at 13151.23,3133.43 h34.45 r45
  text "NC" at 14049.23,3133.43 h34.45 r45
  text "C4" at 14649.23,3133.43 h34.45 r45
  text "E8" at 14957.23,3133.43 h34.45 r45
  text "E2" at 13056.23,3132.43 h34.45 r45
  text "F8" at 15458.23,3127.43 h34.45 r45
  text "F10" at 13550.16,3123.37 h34.45 r45
  text "E10" at 15055.16,3123.37 h34.45 r45
  text "E12" at 15150.16,3120.37 h34.45 r45
  text "B10" at 15345.16,3120.37 h34.45 r45
  text "E14" at 15254.16,3118.37 h34.45 r45
  text "C13" at 13342.16,3116.37 h34.45 r45
  text "GND" at 14338.74,3112.38 h34.45 r45
  text "C15*" at 13433.09,3110.3 h34.45 r45
  text "USER" at 12643.64,3104.83 h45.94
  text "RESET" at 12181.62,3098.83 h45.94
  text "49" at 15438.99,3056.21 h38.28
  text "1" at 13059.58,3054.87 h37.97
  text "11" at 13548.99,3054.76 h38.28
  text "21" at 14040.99,3054.76 h38.28
  text "31" at 14541.99,3054.76 h38.28
  text "41" at 15040.99,3054.76 h38.28
Bottom Silkscreen Layer:
  text "91" at 13457.19,5818.08 h38.28 r315
  text "81" at 13954.19,5817.52 h38.28 r315
  text "71" at 14454.19,5817.52 h38.28 r315
  text "61" at 14949.19,5818.08 h38.28 r315
  text "51" at 15457.19,5817.52 h38.28 r315
  text "99" at 13054.19,5813.42 h38.28 r315
  text "97" at 13155.19,5812.81 h38.28 r315
  text "95" at 13257.19,5812.81 h38.28 r315
  text "93" at 13356.19,5812.81 h38.28 r315
  text "89" at 13557.19,5812.81 h38.28 r315
  text "79" at 14056.19,5812.81 h38.28 r315
  text "69" at 14560.19,5813.42 h38.28 r315
  text "67" at 14659.19,5812.81 h38.28 r315
  text "65" at 14755.19,5812.81 h38.28 r315
  text "63" at 14857.19,5812.81 h38.28 r315
  text "59" at 15050.19,5812.81 h38.28 r315
  text "87" at 13652.19,5812.25 h38.28 r315
  text "85" at 13755.19,5812.25 h38.28 r315
  text "83" at 13853.19,5812.25 h38.28 r315
  text "77" at 14155.19,5812.25 h38.28 r315
  text "75" at 14257.19,5812.25 h38.28 r315
  text "73" at 14353.19,5812.25 h38.28 r315
  text "57" at 15155.19,5812.25 h38.28 r315
  text "55" at 15248.19,5812.25 h38.28 r315
  text "53" at 15354.19,5812.25 h38.28 r315
  text "98" at 13148.19,5544.81 h38.28 r315
  text "96" at 13253.77,5545.42 h38.28 r315
  text "92" at 13455.19,5544.81 h38.28 r315
  text "90" at 13553.19,5544.81 h38.28 r315
  text "86" at 13748.19,5544.81 h38.28 r315
  text "76" at 14246.19,5544.81 h38.28 r315
  text "68" at 14654.19,5544.81 h38.28 r315
  text "66" at 14751.19,5545.42 h38.28 r315
  text "62" at 14952.19,5544.81 h38.28 r315
  text "60" at 15053.19,5544.81 h38.28 r315
  text "56" at 15256.19,5544.81 h38.28 r315
  text "94" at 13349.19,5544.25 h38.28 r315
  text "88" at 13651.19,5544.25 h38.28 r315
  text "84" at 13852.19,5543.65 h38.28 r315
  text "82" at 13949.19,5544.25 h38.28 r315
  text "80" at 14049.19,5544.25 h38.28 r315
  text "78" at 14153.19,5544.25 h38.28 r315
  text "74" at 14349.19,5543.65 h38.28 r315
  text "72" at 14453.19,5544.25 h38.28 r315
  text "70" at 14551.19,5544.25 h38.28 r315
  text "64" at 14855.19,5544.25 h38.28 r315
  text "58" at 15155.19,5544.25 h38.28 r315
  text "54" at 15359.19,5543.65 h38.28 r315
  text "52" at 15462.19,5544.25 h38.28 r315
  text "100" at 13053,5535.21 h38.28 r315
  text "VCC" at 11649.01,4223.23 h34.45 r270
  text "AT32F423VCT7" at 14039.38,3746.39 h114.84
  text "6" at 13250.19,3430.88 h37.97 r315
  text "2" at 13052.6,3430.31 h37.97 r315
  text "4" at 13153.52,3429.74 h37.97 r315
  text "8" at 13346.98,3430.31 h37.97 r315
  text "16" at 13756.7,3421.68 h38.28 r315
  text "10" at 13454.4,3421.12 h38.28 r315
  text "12" at 13555.81,3421.12 h38.28 r315
  text "14" at 13660.19,3420.52 h38.28 r315
  text "18" at 13858.12,3421.12 h38.28 r315
  text "20" at 13956.07,3415.85 h38.28 r315
  text "22" at 14055.01,3415.85 h38.28 r315
  text "26" at 14256.19,3416.42 h38.28 r315
  text "28" at 14356.19,3415.85 h38.28 r315
  text "30" at 14456.19,3415.85 h38.28 r315
  text "32" at 14563.19,3415.85 h38.28 r315
  text "36" at 14763.19,3416.42 h38.28 r315
  text "38" at 14863.19,3415.85 h38.28 r315
  text "46" at 15264.19,3415.85 h38.28 r315
  text "50" at 15459.19,3415.85 h38.28 r315
  text "24" at 14160.16,3415.25 h38.28 r315
  text "34" at 14665.19,3415.25 h38.28 r315
  text "40" at 14969.19,3415.25 h38.28 r315
  text "42" at 15066.19,3415.25 h38.28 r315
  text "44" at 15164.19,3414.68 h38.28 r315
  text "48" at 15359.19,3415.25 h38.28 r315
  text "1" at 13035.6,3160.91 h37.97 r315
  text "3" at 13137.73,3155.71 h37.97 r315
  text "5" at 13238.87,3155.71 h37.97 r315
  text "7" at 13341.01,3155.71 h37.97 r315
  text "9" at 13438.01,3156.28 h37.97 r315
  text "11" at 13536.23,3151.78 h38.28 r315
  text "13" at 13645.99,3146.52 h38.28 r315
  text "15" at 13747.74,3146.52 h38.28 r315
  text "17" at 13850.5,3146.52 h38.28 r315
  text "19" at 13947.12,3147.08 h38.28 r315
  text "21" at 14048.87,3146.52 h38.28 r315
  text "31" at 14555.19,3146.52 h38.28 r315
  text "41" at 15052.19,3145.92 h38.28 r315
  text "29" at 14459.19,3141.81 h38.28 r315
  text "39" at 14956.19,3141.81 h38.28 r315
  text "23" at 14156.16,3141.25 h38.28 r315
  text "25" at 14255.19,3141.25 h38.28 r315
  text "27" at 14355.19,3141.25 h38.28 r315
  text "33" at 14653.19,3141.25 h38.28 r315
  text "35" at 14753.19,3141.25 h38.28 r315
  text "37" at 14851.19,3141.25 h38.28 r315
  text "43" at 15154.19,3140.65 h38.28 r315
  text "45" at 15252.19,3140.65 h38.28 r315
  text "47" at 15354.19,3140.65 h38.28 r315
  text "49" at 15456.19,3141.25 h38.28 r315
Mechanical Layer:
  circle w1: c15760.05,5897.28 r62.99
  circle w1: c15760.05,3122.6 r62.99
  circle w1: c12019.89,3122.6 r62.99
  circle w1: c12019.89,5897.28 r62.99
  circle w1: c15019.5,4860.43 r62.99
  circle w1: c12969.5,3560.43 r62.99
  circle w1: c13019.5,5460.43 r62.99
